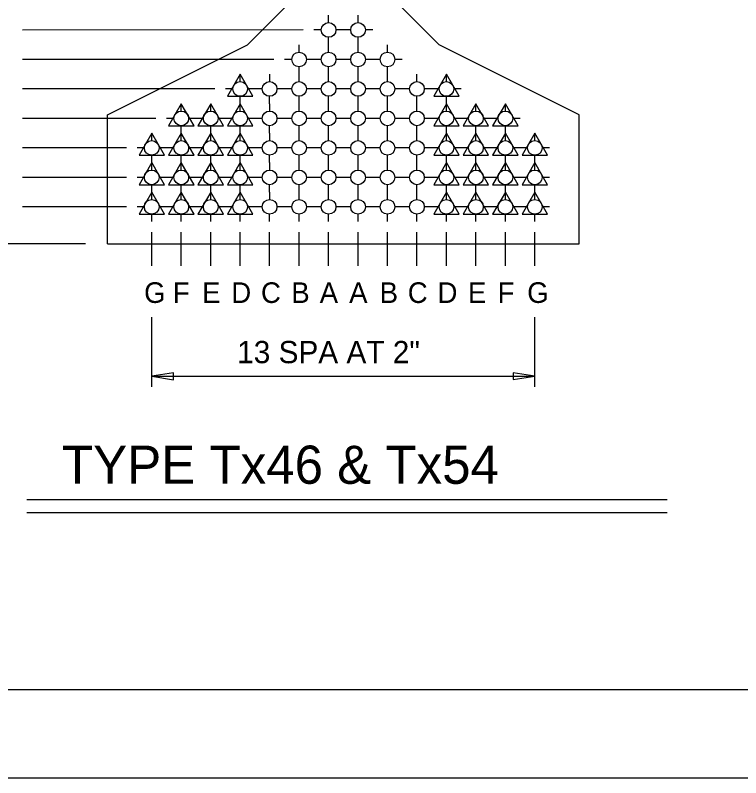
# Model space of a CAD drawing. Extents: x 998.6 to 1033.3, y 1000 to 1011.
# Drawn here: x 1005.798 to 1007.849, y 1000 to 1002.156 of the extents above; entities that cross this region are included whole.
import ezdxf

# ---------------------------------------------------------------- set-up
doc = ezdxf.new("R2010")
doc.units = 0
for name, color, linetype in [('D_BATCH_PLOT', 7, 'Continuous'), ('D_SHEET', 7, 'Continuous'), ('Working Level 1', 7, 'Continuous')]:
    doc.layers.add(name, color=color, linetype=linetype)

msp = doc.modelspace()

# ---------------------------------------------------------------- linework, layer by layer
at = {"layer": 'D_BATCH_PLOT'}
msp.add_lwpolyline([(1000, 1000), (1017, 1000), (1017, 1011), (1000, 1011)], close=True, dxfattribs=at)
at = {"layer": 'D_SHEET'}
for p, q in [((1001, 1000.25), (1016.75, 1000.25)), ((1000, 1000), (1017, 1000))]:
    msp.add_line(p, q, dxfattribs=at)
at = {"layer": 'Working Level 1'}
for p, q in [((1006.4545, 1002.0727), (1006.5795, 1002.1977)), ((1006.9962, 1002.0727), (1006.8712, 1002.1977)), ((1006.6838, 1002.1353), (1006.6838, 1002.1561)), ((1006.7671, 1002.1353), (1006.7671, 1002.1561)), ((1006.6121, 1002.1145), (1005.8182, 1002.1144)), ((1006.6629, 1002.1145), (1006.6421, 1002.1145)), ((1006.7254, 1002.1145), (1006.7046, 1002.1145)), ((1006.7462, 1002.1145), (1006.7254, 1002.1145)), ((1006.8087, 1002.1145), (1006.7879, 1002.1145)), ((1006.6837, 1002.0728), (1006.6837, 1002.0936)), ((1006.767, 1002.0728), (1006.767, 1002.0936)), ((1006.0587, 1001.8748), (1006.4545, 1002.0727)), ((1006.6005, 1002.0519), (1006.6005, 1002.0728)), ((1006.6838, 1002.0519), (1006.6838, 1002.0728)), ((1006.7671, 1002.0519), (1006.7671, 1002.0728)), ((1006.8505, 1002.0519), (1006.8505, 1002.0728)), ((1007.3921, 1001.8748), (1006.9962, 1002.0727)), ((1006.5288, 1002.0311), (1005.8182, 1002.031)), ((1006.5796, 1002.0311), (1006.5588, 1002.0311)), ((1006.6421, 1002.0311), (1006.6213, 1002.0311)), ((1006.6629, 1002.0311), (1006.6421, 1002.0311)), ((1006.7254, 1002.0311), (1006.7046, 1002.0311)), ((1006.7462, 1002.0311), (1006.7254, 1002.0311)), ((1006.8087, 1002.0311), (1006.7879, 1002.0311)), ((1006.8296, 1002.0311), (1006.8088, 1002.0311)), ((1006.8921, 1002.0311), (1006.8713, 1002.0311)), ((1006.6004, 1001.9894), (1006.6004, 1002.0103)), ((1006.6837, 1001.9894), (1006.6837, 1002.0103)), ((1006.767, 1001.9894), (1006.767, 1002.0103)), ((1006.8504, 1001.9894), (1006.8504, 1002.0103)), ((1006.4338, 1001.9894), (1006.3976, 1001.9269)), ((1006.4338, 1001.9686), (1006.4338, 1001.9894)), ((1006.4698, 1001.9269), (1006.4338, 1001.9894)), ((1006.5171, 1001.9686), (1006.5171, 1001.9894)), ((1006.6004, 1001.9686), (1006.6004, 1001.9894)), ((1006.6838, 1001.9686), (1006.6838, 1001.9894)), ((1006.7671, 1001.9686), (1006.7671, 1001.9894)), ((1006.8504, 1001.9686), (1006.8504, 1001.9894)), ((1006.9338, 1001.9686), (1006.9338, 1001.9894)), ((1007.0172, 1001.9894), (1006.981, 1001.9269)), ((1007.0172, 1001.9686), (1007.0172, 1001.9894)), ((1007.0532, 1001.9269), (1007.0172, 1001.9894)), ((1006.3621, 1001.9478), (1005.8182, 1001.9477)), ((1006.4129, 1001.9477), (1006.3921, 1001.9477)), ((1006.4754, 1001.9477), (1006.4546, 1001.9477)), ((1006.4962, 1001.9478), (1006.4754, 1001.9478)), ((1006.5587, 1001.9478), (1006.5379, 1001.9478)), ((1006.5796, 1001.9478), (1006.5587, 1001.9478)), ((1006.6421, 1001.9478), (1006.6212, 1001.9478)), ((1006.6629, 1001.9478), (1006.6421, 1001.9478)), ((1006.7254, 1001.9478), (1006.7046, 1001.9478)), ((1006.7462, 1001.9478), (1006.7254, 1001.9478)), ((1006.8087, 1001.9478), (1006.7879, 1001.9478)), ((1006.8296, 1001.9478), (1006.8087, 1001.9478)), ((1006.8921, 1001.9478), (1006.8712, 1001.9478)), ((1006.9129, 1001.9478), (1006.8921, 1001.9478)), ((1006.9754, 1001.9478), (1006.9546, 1001.9478)), ((1006.9963, 1001.9477), (1006.9755, 1001.9477)), ((1007.0588, 1001.9477), (1007.038, 1001.9477)), ((1006.3976, 1001.9269), (1006.4698, 1001.9269)), ((1006.4337, 1001.9061), (1006.4337, 1001.9269)), ((1006.517, 1001.9061), (1006.517, 1001.9269)), ((1006.6004, 1001.9061), (1006.6004, 1001.9269)), ((1006.6837, 1001.9061), (1006.6837, 1001.9269)), ((1006.767, 1001.9061), (1006.767, 1001.9269)), ((1006.8504, 1001.9061), (1006.8504, 1001.9269)), ((1006.9337, 1001.9061), (1006.9337, 1001.9269)), ((1006.981, 1001.9269), (1007.0532, 1001.9269)), ((1007.0171, 1001.9061), (1007.0171, 1001.9269)), ((1006.2671, 1001.9061), (1006.2309, 1001.8436)), ((1006.2671, 1001.8852), (1006.2671, 1001.9061)), ((1006.3031, 1001.8436), (1006.2671, 1001.9061)), ((1006.3504, 1001.9061), (1006.3143, 1001.8436)), ((1006.3504, 1001.8852), (1006.3504, 1001.9061)), ((1006.3864, 1001.8436), (1006.3504, 1001.9061)), ((1006.4337, 1001.9061), (1006.3976, 1001.8436)), ((1006.4337, 1001.8852), (1006.4337, 1001.9061)), ((1006.4698, 1001.8436), (1006.4337, 1001.9061)), ((1006.5171, 1001.8852), (1006.5171, 1001.9061)), ((1006.6004, 1001.8852), (1006.6004, 1001.9061)), ((1006.6838, 1001.8852), (1006.6838, 1001.9061)), ((1006.7671, 1001.8852), (1006.7671, 1001.9061)), ((1006.8504, 1001.8852), (1006.8504, 1001.9061)), ((1006.9338, 1001.8852), (1006.9338, 1001.9061)), ((1007.0171, 1001.9061), (1006.981, 1001.8436)), ((1007.0171, 1001.8852), (1007.0171, 1001.9061)), ((1007.0532, 1001.8436), (1007.0171, 1001.9061)), ((1007.1005, 1001.9061), (1007.0644, 1001.8436)), ((1007.1005, 1001.8852), (1007.1005, 1001.9061)), ((1007.1365, 1001.8436), (1007.1005, 1001.9061)), ((1007.1839, 1001.9061), (1007.1477, 1001.8436)), ((1007.1839, 1001.8852), (1007.1839, 1001.9061)), ((1007.2199, 1001.8436), (1007.1839, 1001.9061)), ((1006.0587, 1001.5102), (1006.0587, 1001.8748)), ((1007.3921, 1001.5102), (1007.3921, 1001.8748)), ((1006.1954, 1001.8644), (1005.8182, 1001.8643)), ((1006.2462, 1001.8644), (1006.2254, 1001.8644)), ((1006.3087, 1001.8644), (1006.2879, 1001.8644)), ((1006.3295, 1001.8644), (1006.3087, 1001.8644)), ((1006.392, 1001.8644), (1006.3712, 1001.8644)), ((1006.4129, 1001.8644), (1006.392, 1001.8644)), ((1006.4754, 1001.8644), (1006.4545, 1001.8644)), ((1006.4962, 1001.8644), (1006.4754, 1001.8644)), ((1006.5587, 1001.8644), (1006.5379, 1001.8644)), ((1006.5796, 1001.8644), (1006.5587, 1001.8644)), ((1006.6421, 1001.8644), (1006.6212, 1001.8644)), ((1006.6629, 1001.8644), (1006.6421, 1001.8644)), ((1006.7254, 1001.8644), (1006.7046, 1001.8644)), ((1006.7462, 1001.8644), (1006.7254, 1001.8644)), ((1006.8087, 1001.8644), (1006.7879, 1001.8644)), ((1006.8296, 1001.8644), (1006.8087, 1001.8644)), ((1006.8921, 1001.8644), (1006.8712, 1001.8644)), ((1006.9129, 1001.8644), (1006.8921, 1001.8644)), ((1006.9754, 1001.8644), (1006.9546, 1001.8644)), ((1006.9963, 1001.8644), (1006.9754, 1001.8644)), ((1007.0588, 1001.8644), (1007.0379, 1001.8644)), ((1007.0796, 1001.8644), (1007.0588, 1001.8644)), ((1007.1421, 1001.8644), (1007.1213, 1001.8644)), ((1007.163, 1001.8644), (1007.1422, 1001.8644)), ((1007.2255, 1001.8644), (1007.2047, 1001.8644)), ((1006.2309, 1001.8436), (1006.3031, 1001.8436)), ((1006.267, 1001.8227), (1006.267, 1001.8436)), ((1006.3143, 1001.8436), (1006.3864, 1001.8436)), ((1006.3503, 1001.8227), (1006.3503, 1001.8436)), ((1006.3976, 1001.8436), (1006.4698, 1001.8436)), ((1006.4337, 1001.8227), (1006.4337, 1001.8436)), ((1006.517, 1001.8227), (1006.517, 1001.8436)), ((1006.6004, 1001.8227), (1006.6004, 1001.8436)), ((1006.6837, 1001.8227), (1006.6837, 1001.8436)), ((1006.767, 1001.8227), (1006.767, 1001.8436)), ((1006.8504, 1001.8227), (1006.8504, 1001.8436)), ((1006.9337, 1001.8227), (1006.9337, 1001.8436)), ((1006.981, 1001.8436), (1007.0532, 1001.8436)), ((1007.0171, 1001.8227), (1007.0171, 1001.8436)), ((1007.0644, 1001.8436), (1007.1365, 1001.8436)), ((1007.1004, 1001.8227), (1007.1004, 1001.8436)), ((1007.1477, 1001.8436), (1007.2199, 1001.8436)), ((1007.1838, 1001.8227), (1007.1838, 1001.8436)), ((1006.1837, 1001.8227), (1006.1476, 1001.7602)), ((1006.1837, 1001.8019), (1006.1837, 1001.8227)), ((1006.2197, 1001.7602), (1006.1837, 1001.8227)), ((1006.267, 1001.8227), (1006.2309, 1001.7602)), ((1006.267, 1001.8019), (1006.267, 1001.8227)), ((1006.3031, 1001.7602), (1006.267, 1001.8227)), ((1006.3504, 1001.8227), (1006.3143, 1001.7602)), ((1006.3504, 1001.8019), (1006.3504, 1001.8227)), ((1006.3864, 1001.7602), (1006.3504, 1001.8227)), ((1006.4337, 1001.8227), (1006.3976, 1001.7602)), ((1006.4337, 1001.8019), (1006.4337, 1001.8227)), ((1006.4698, 1001.7602), (1006.4337, 1001.8227)), ((1006.5171, 1001.8019), (1006.5171, 1001.8227)), ((1006.6004, 1001.8019), (1006.6004, 1001.8227)), ((1006.6838, 1001.8019), (1006.6838, 1001.8227)), ((1006.7671, 1001.8019), (1006.7671, 1001.8227)), ((1006.8504, 1001.8019), (1006.8504, 1001.8227)), ((1006.9338, 1001.8019), (1006.9338, 1001.8227)), ((1007.0171, 1001.8227), (1006.981, 1001.7602)), ((1007.0171, 1001.8019), (1007.0171, 1001.8227)), ((1007.0532, 1001.7602), (1007.0171, 1001.8227)), ((1007.1005, 1001.8227), (1007.0644, 1001.7602)), ((1007.1005, 1001.8019), (1007.1005, 1001.8227)), ((1007.1365, 1001.7602), (1007.1005, 1001.8227)), ((1007.1838, 1001.8227), (1007.1477, 1001.7602)), ((1007.1838, 1001.8019), (1007.1838, 1001.8227)), ((1007.2199, 1001.7602), (1007.1838, 1001.8227)), ((1007.2672, 1001.8227), (1007.2311, 1001.7602)), ((1007.2672, 1001.8019), (1007.2672, 1001.8227)), ((1007.3032, 1001.7602), (1007.2672, 1001.8227)), ((1006.112, 1001.7811), (1005.8182, 1001.781)), ((1006.1628, 1001.7811), (1006.142, 1001.7811)), ((1006.2253, 1001.7811), (1006.2045, 1001.7811)), ((1006.2462, 1001.7811), (1006.2253, 1001.7811)), ((1006.3087, 1001.7811), (1006.2878, 1001.7811)), ((1006.3295, 1001.7811), (1006.3087, 1001.7811)), ((1006.392, 1001.7811), (1006.3712, 1001.7811)), ((1006.4129, 1001.7811), (1006.392, 1001.7811)), ((1006.4754, 1001.7811), (1006.4545, 1001.7811)), ((1006.4962, 1001.7811), (1006.4754, 1001.7811)), ((1006.5587, 1001.7811), (1006.5379, 1001.7811)), ((1006.5796, 1001.7811), (1006.5587, 1001.7811)), ((1006.6421, 1001.7811), (1006.6212, 1001.7811)), ((1006.6629, 1001.7811), (1006.6421, 1001.7811)), ((1006.7254, 1001.7811), (1006.7046, 1001.7811)), ((1006.7462, 1001.7811), (1006.7254, 1001.7811)), ((1006.8087, 1001.7811), (1006.7879, 1001.7811)), ((1006.8296, 1001.7811), (1006.8087, 1001.7811)), ((1006.8921, 1001.7811), (1006.8712, 1001.7811)), ((1006.9129, 1001.7811), (1006.8921, 1001.7811)), ((1006.9754, 1001.7811), (1006.9546, 1001.7811)), ((1006.9963, 1001.7811), (1006.9754, 1001.7811)), ((1007.0588, 1001.7811), (1007.0379, 1001.7811)), ((1007.0796, 1001.7811), (1007.0588, 1001.7811)), ((1007.1421, 1001.7811), (1007.1213, 1001.7811)), ((1007.163, 1001.7811), (1007.1421, 1001.7811)), ((1007.2255, 1001.7811), (1007.2046, 1001.7811)), ((1007.2463, 1001.7811), (1007.2255, 1001.7811)), ((1007.3088, 1001.7811), (1007.288, 1001.7811)), ((1006.1476, 1001.7602), (1006.2197, 1001.7602)), ((1006.1837, 1001.7394), (1006.1476, 1001.6769)), ((1006.1836, 1001.7394), (1006.1836, 1001.7602)), ((1006.1837, 1001.7185), (1006.1837, 1001.7394)), ((1006.2197, 1001.6769), (1006.1837, 1001.7394)), ((1006.2309, 1001.7602), (1006.3031, 1001.7602)), ((1006.267, 1001.7394), (1006.2309, 1001.6769)), ((1006.267, 1001.7394), (1006.267, 1001.7602)), ((1006.267, 1001.7185), (1006.267, 1001.7394)), ((1006.3031, 1001.6769), (1006.267, 1001.7394)), ((1006.3143, 1001.7602), (1006.3864, 1001.7602)), ((1006.3504, 1001.7394), (1006.3143, 1001.6769)), ((1006.3503, 1001.7394), (1006.3503, 1001.7602)), ((1006.3504, 1001.7185), (1006.3504, 1001.7394)), ((1006.3864, 1001.6769), (1006.3504, 1001.7394)), ((1006.3976, 1001.7602), (1006.4698, 1001.7602)), ((1006.4337, 1001.7394), (1006.3976, 1001.6769)), ((1006.4337, 1001.7394), (1006.4337, 1001.7602)), ((1006.4337, 1001.7185), (1006.4337, 1001.7394)), ((1006.4698, 1001.6769), (1006.4337, 1001.7394)), ((1006.517, 1001.7394), (1006.517, 1001.7602)), ((1006.5171, 1001.7185), (1006.5171, 1001.7394)), ((1006.6004, 1001.7394), (1006.6004, 1001.7602)), ((1006.6004, 1001.7185), (1006.6004, 1001.7394)), ((1006.6837, 1001.7394), (1006.6837, 1001.7602)), ((1006.6838, 1001.7185), (1006.6838, 1001.7394)), ((1006.767, 1001.7394), (1006.767, 1001.7602)), ((1006.7671, 1001.7185), (1006.7671, 1001.7394)), ((1006.8504, 1001.7394), (1006.8504, 1001.7602)), ((1006.8504, 1001.7185), (1006.8504, 1001.7394)), ((1006.9337, 1001.7394), (1006.9337, 1001.7602)), ((1006.9338, 1001.7185), (1006.9338, 1001.7394)), ((1006.981, 1001.7602), (1007.0532, 1001.7602)), ((1007.0171, 1001.7394), (1006.981, 1001.6769)), ((1007.0171, 1001.7394), (1007.0171, 1001.7602)), ((1007.0171, 1001.7185), (1007.0171, 1001.7394)), ((1007.0532, 1001.6769), (1007.0171, 1001.7394)), ((1007.0644, 1001.7602), (1007.1365, 1001.7602)), ((1007.1005, 1001.7394), (1007.0644, 1001.6769)), ((1007.1004, 1001.7394), (1007.1004, 1001.7602)), ((1007.1005, 1001.7185), (1007.1005, 1001.7394)), ((1007.1365, 1001.6769), (1007.1005, 1001.7394)), ((1007.1477, 1001.7602), (1007.2199, 1001.7602)), ((1007.1838, 1001.7394), (1007.1477, 1001.6769)), ((1007.1838, 1001.7394), (1007.1838, 1001.7602)), ((1007.1838, 1001.7185), (1007.1838, 1001.7394)), ((1007.2199, 1001.6769), (1007.1838, 1001.7394)), ((1007.2311, 1001.7602), (1007.3032, 1001.7602)), ((1007.2672, 1001.7394), (1007.2311, 1001.6769)), ((1007.2671, 1001.7394), (1007.2671, 1001.7602)), ((1007.2672, 1001.7185), (1007.2672, 1001.7394)), ((1007.3032, 1001.6769), (1007.2672, 1001.7394)), ((1006.112, 1001.6977), (1005.8182, 1001.6976)), ((1006.1628, 1001.6977), (1006.142, 1001.6977)), ((1006.2253, 1001.6977), (1006.2045, 1001.6977)), ((1006.2462, 1001.6977), (1006.2253, 1001.6977)), ((1006.3087, 1001.6977), (1006.2878, 1001.6977)), ((1006.3295, 1001.6977), (1006.3087, 1001.6977)), ((1006.392, 1001.6977), (1006.3712, 1001.6977)), ((1006.4129, 1001.6977), (1006.392, 1001.6977)), ((1006.4754, 1001.6977), (1006.4545, 1001.6977)), ((1006.4962, 1001.6977), (1006.4754, 1001.6977)), ((1006.5587, 1001.6977), (1006.5379, 1001.6977)), ((1006.5796, 1001.6977), (1006.5587, 1001.6977)), ((1006.6421, 1001.6977), (1006.6212, 1001.6977)), ((1006.6629, 1001.6977), (1006.6421, 1001.6977)), ((1006.7254, 1001.6977), (1006.7046, 1001.6977)), ((1006.7462, 1001.6977), (1006.7254, 1001.6977)), ((1006.8087, 1001.6977), (1006.7879, 1001.6977)), ((1006.8296, 1001.6977), (1006.8087, 1001.6977)), ((1006.8921, 1001.6977), (1006.8712, 1001.6977)), ((1006.9129, 1001.6977), (1006.8921, 1001.6977)), ((1006.9754, 1001.6977), (1006.9546, 1001.6977)), ((1006.9963, 1001.6977), (1006.9754, 1001.6977)), ((1007.0588, 1001.6977), (1007.0379, 1001.6977)), ((1007.0796, 1001.6977), (1007.0588, 1001.6977)), ((1007.1421, 1001.6977), (1007.1213, 1001.6977)), ((1007.163, 1001.6977), (1007.1421, 1001.6977)), ((1007.2255, 1001.6977), (1007.2046, 1001.6977)), ((1007.2463, 1001.6977), (1007.2255, 1001.6977)), ((1007.3088, 1001.6977), (1007.288, 1001.6977)), ((1006.1476, 1001.6769), (1006.2197, 1001.6769)), ((1006.1836, 1001.656), (1006.1836, 1001.6769)), ((1006.2309, 1001.6769), (1006.3031, 1001.6769)), ((1006.267, 1001.656), (1006.267, 1001.6769)), ((1006.3143, 1001.6769), (1006.3864, 1001.6769)), ((1006.3503, 1001.656), (1006.3503, 1001.6769)), ((1006.3976, 1001.6769), (1006.4698, 1001.6769)), ((1006.4337, 1001.656), (1006.4337, 1001.6769)), ((1006.517, 1001.656), (1006.517, 1001.6769)), ((1006.6004, 1001.656), (1006.6004, 1001.6769)), ((1006.6837, 1001.656), (1006.6837, 1001.6769)), ((1006.767, 1001.656), (1006.767, 1001.6769)), ((1006.8504, 1001.656), (1006.8504, 1001.6769)), ((1006.9337, 1001.656), (1006.9337, 1001.6769)), ((1006.981, 1001.6769), (1007.0532, 1001.6769)), ((1007.0171, 1001.656), (1007.0171, 1001.6769)), ((1007.0644, 1001.6769), (1007.1365, 1001.6769)), ((1007.1004, 1001.656), (1007.1004, 1001.6769)), ((1007.1477, 1001.6769), (1007.2199, 1001.6769)), ((1007.1838, 1001.656), (1007.1838, 1001.6769)), ((1007.2311, 1001.6769), (1007.3032, 1001.6769)), ((1007.2671, 1001.656), (1007.2671, 1001.6769)), ((1006.1837, 1001.656), (1006.1476, 1001.5935)), ((1006.1837, 1001.6352), (1006.1837, 1001.656)), ((1006.2197, 1001.5935), (1006.1837, 1001.656)), ((1006.267, 1001.656), (1006.2309, 1001.5935)), ((1006.267, 1001.6352), (1006.267, 1001.656)), ((1006.3031, 1001.5935), (1006.267, 1001.656)), ((1006.3504, 1001.656), (1006.3143, 1001.5935)), ((1006.3504, 1001.6352), (1006.3504, 1001.656)), ((1006.3864, 1001.5935), (1006.3504, 1001.656)), ((1006.4337, 1001.656), (1006.3976, 1001.5935)), ((1006.4337, 1001.6352), (1006.4337, 1001.656)), ((1006.4698, 1001.5935), (1006.4337, 1001.656)), ((1006.5171, 1001.6352), (1006.5171, 1001.656)), ((1006.6004, 1001.6352), (1006.6004, 1001.656)), ((1006.6838, 1001.6352), (1006.6838, 1001.656)), ((1006.7671, 1001.6352), (1006.7671, 1001.656)), ((1006.8504, 1001.6352), (1006.8504, 1001.656)), ((1006.9338, 1001.6352), (1006.9338, 1001.656)), ((1007.0171, 1001.656), (1006.981, 1001.5935)), ((1007.0171, 1001.6352), (1007.0171, 1001.656)), ((1007.0532, 1001.5935), (1007.0171, 1001.656)), ((1007.1005, 1001.656), (1007.0644, 1001.5935)), ((1007.1005, 1001.6352), (1007.1005, 1001.656)), ((1007.1365, 1001.5935), (1007.1005, 1001.656)), ((1007.1838, 1001.656), (1007.1477, 1001.5935)), ((1007.1838, 1001.6352), (1007.1838, 1001.656)), ((1007.2199, 1001.5935), (1007.1838, 1001.656)), ((1007.2672, 1001.656), (1007.2311, 1001.5935)), ((1007.2672, 1001.6352), (1007.2672, 1001.656)), ((1007.3032, 1001.5935), (1007.2672, 1001.656)), ((1006.112, 1001.6144), (1005.8182, 1001.6143)), ((1006.1628, 1001.6144), (1006.142, 1001.6144)), ((1006.2253, 1001.6144), (1006.2045, 1001.6144)), ((1006.2462, 1001.6144), (1006.2253, 1001.6144)), ((1006.3087, 1001.6144), (1006.2878, 1001.6144)), ((1006.3295, 1001.6144), (1006.3087, 1001.6144)), ((1006.392, 1001.6144), (1006.3712, 1001.6144)), ((1006.4129, 1001.6144), (1006.392, 1001.6144)), ((1006.4754, 1001.6144), (1006.4545, 1001.6144)), ((1006.4962, 1001.6144), (1006.4754, 1001.6144)), ((1006.5587, 1001.6144), (1006.5379, 1001.6144)), ((1006.5796, 1001.6144), (1006.5587, 1001.6144)), ((1006.6421, 1001.6144), (1006.6212, 1001.6144)), ((1006.6629, 1001.6144), (1006.6421, 1001.6144)), ((1006.7254, 1001.6144), (1006.7046, 1001.6144)), ((1006.7462, 1001.6144), (1006.7254, 1001.6144)), ((1006.8087, 1001.6144), (1006.7879, 1001.6144)), ((1006.8296, 1001.6144), (1006.8087, 1001.6144)), ((1006.8921, 1001.6144), (1006.8712, 1001.6144)), ((1006.9129, 1001.6144), (1006.8921, 1001.6144)), ((1006.9754, 1001.6144), (1006.9546, 1001.6144)), ((1006.9963, 1001.6144), (1006.9754, 1001.6144)), ((1007.0588, 1001.6144), (1007.0379, 1001.6144)), ((1007.0796, 1001.6144), (1007.0588, 1001.6144)), ((1007.1421, 1001.6144), (1007.1213, 1001.6144)), ((1007.163, 1001.6144), (1007.1421, 1001.6144)), ((1007.2255, 1001.6144), (1007.2046, 1001.6144)), ((1007.2463, 1001.6144), (1007.2255, 1001.6144)), ((1007.3088, 1001.6144), (1007.288, 1001.6144)), ((1006.1476, 1001.5935), (1006.2197, 1001.5935)), ((1006.1836, 1001.5727), (1006.1836, 1001.5935)), ((1006.2309, 1001.5935), (1006.3031, 1001.5935)), ((1006.267, 1001.5727), (1006.267, 1001.5935)), ((1006.3143, 1001.5935), (1006.3864, 1001.5935)), ((1006.3503, 1001.5727), (1006.3503, 1001.5935)), ((1006.3976, 1001.5935), (1006.4698, 1001.5935)), ((1006.4337, 1001.5727), (1006.4337, 1001.5935)), ((1006.517, 1001.5727), (1006.517, 1001.5935)), ((1006.6004, 1001.5727), (1006.6004, 1001.5935)), ((1006.6837, 1001.5727), (1006.6837, 1001.5935)), ((1006.767, 1001.5727), (1006.767, 1001.5935)), ((1006.8504, 1001.5727), (1006.8504, 1001.5935)), ((1006.9337, 1001.5727), (1006.9337, 1001.5935)), ((1006.981, 1001.5935), (1007.0532, 1001.5935)), ((1007.0171, 1001.5727), (1007.0171, 1001.5935)), ((1007.0644, 1001.5935), (1007.1365, 1001.5935)), ((1007.1004, 1001.5727), (1007.1004, 1001.5935)), ((1007.1477, 1001.5935), (1007.2199, 1001.5935)), ((1007.1838, 1001.5727), (1007.1838, 1001.5935)), ((1007.2311, 1001.5935), (1007.3032, 1001.5935)), ((1007.2671, 1001.5727), (1007.2671, 1001.5935)), ((1006.1836, 1001.4477), (1006.1836, 1001.5427)), ((1006.267, 1001.4477), (1006.267, 1001.5427)), ((1006.3503, 1001.4477), (1006.3503, 1001.5427)), ((1006.4337, 1001.4477), (1006.4337, 1001.5427)), ((1006.517, 1001.4477), (1006.517, 1001.5427)), ((1006.6004, 1001.4477), (1006.6004, 1001.5427)), ((1006.6837, 1001.4477), (1006.6837, 1001.5427)), ((1006.767, 1001.4477), (1006.767, 1001.5427)), ((1006.8504, 1001.4477), (1006.8504, 1001.5427)), ((1006.9337, 1001.4477), (1006.9337, 1001.5427)), ((1007.0171, 1001.4477), (1007.0171, 1001.5427)), ((1007.1004, 1001.4477), (1007.1004, 1001.5427)), ((1007.1838, 1001.4477), (1007.1838, 1001.5427)), ((1007.2671, 1001.4477), (1007.2671, 1001.5427)), ((1005.9962, 1001.5102), (1005.4429, 1001.5101)), ((1006.0587, 1001.5102), (1007.3921, 1001.5102)), ((1006.1836, 1001.1052), (1006.1836, 1001.302)), ((1007.2671, 1001.1052), (1007.2671, 1001.302)), ((1006.1836, 1001.1352), (1007.2671, 1001.1352)), ((1005.8302, 1000.7866), (1007.641, 1000.7866)), ((1005.8302, 1000.75), (1007.641, 1000.75))]:
    msp.add_line(p, q, dxfattribs=at)
for points in [[(1006.1836, 1001.1352), (1006.2449, 1001.1252), (1006.2449, 1001.1446)], [(1007.2671, 1001.1352), (1007.2059, 1001.1452), (1007.2059, 1001.1258)]]:
    msp.add_lwpolyline(points, close=True, dxfattribs=at)
for centre in [(1006.6837, 1002.1145), (1006.767, 1002.1145), (1006.6004, 1002.0311), (1006.6837, 1002.0311), (1006.767, 1002.0311), (1006.8504, 1002.0311), (1006.4337, 1001.9477), (1006.517, 1001.9478), (1006.6004, 1001.9478), (1006.6837, 1001.9478), (1006.767, 1001.9478), (1006.8504, 1001.9478), (1006.9337, 1001.9478), (1007.0171, 1001.9477), (1006.267, 1001.8644), (1006.3503, 1001.8644), (1006.4337, 1001.8644), (1006.517, 1001.8644), (1006.6004, 1001.8644), (1006.6837, 1001.8644), (1006.767, 1001.8644), (1006.8504, 1001.8644), (1006.9337, 1001.8644), (1007.0171, 1001.8644), (1007.1004, 1001.8644), (1007.1838, 1001.8644), (1006.1836, 1001.7811), (1006.267, 1001.7811), (1006.3503, 1001.7811), (1006.4337, 1001.7811), (1006.517, 1001.7811), (1006.6004, 1001.7811), (1006.6837, 1001.7811), (1006.767, 1001.7811), (1006.8504, 1001.7811), (1006.9337, 1001.7811), (1007.0171, 1001.7811), (1007.1004, 1001.7811), (1007.1838, 1001.7811), (1007.2671, 1001.7811), (1006.1836, 1001.6977), (1006.267, 1001.6977), (1006.3503, 1001.6977), (1006.4337, 1001.6977), (1006.517, 1001.6977), (1006.6004, 1001.6977), (1006.6837, 1001.6977), (1006.767, 1001.6977), (1006.8504, 1001.6977), (1006.9337, 1001.6977), (1007.0171, 1001.6977), (1007.1004, 1001.6977), (1007.1838, 1001.6977), (1007.2671, 1001.6977), (1006.1836, 1001.6144), (1006.267, 1001.6144), (1006.3503, 1001.6144), (1006.4337, 1001.6144), (1006.517, 1001.6144), (1006.6004, 1001.6144), (1006.6837, 1001.6144), (1006.767, 1001.6144), (1006.8504, 1001.6144), (1006.9337, 1001.6144), (1007.0171, 1001.6144), (1007.1004, 1001.6144), (1007.1838, 1001.6144), (1007.2671, 1001.6144)]:
    msp.add_circle(centre, 0.0208, dxfattribs=at)

# ---------------------------------------------------------------- texts
for s, height, p in [('G', 0.0583, (1006.162, 1001.3427)), ('F', 0.0583, (1006.243, 1001.3423)), ('E', 0.0583, (1006.3262, 1001.3426)), ('D', 0.0583, (1006.4086, 1001.3426)), ('C', 0.0583, (1006.4925, 1001.3426)), ('B', 0.0583, (1006.5782, 1001.3426)), ('A', 0.0583, (1006.6586, 1001.3426)), ('A', 0.0583, (1006.7419, 1001.3426)), ('B', 0.0583, (1006.8282, 1001.3426)), ('C', 0.0583, (1006.9077, 1001.3426)), ('D', 0.0583, (1006.9919, 1001.3426)), ('E', 0.0583, (1007.0778, 1001.3426)), ('F', 0.0583, (1007.1618, 1001.3427)), ('G', 0.0583, (1007.2455, 1001.3427)), ('13 SPA AT 2"', 0.063, (1006.4252, 1001.1722)), ('TYPE Tx46 & Tx54', 0.108, (1005.9296, 1000.8312))]:
    msp.add_text(s, height=height, dxfattribs=at).set_placement(p)

doc.saveas('drawing.dxf')
